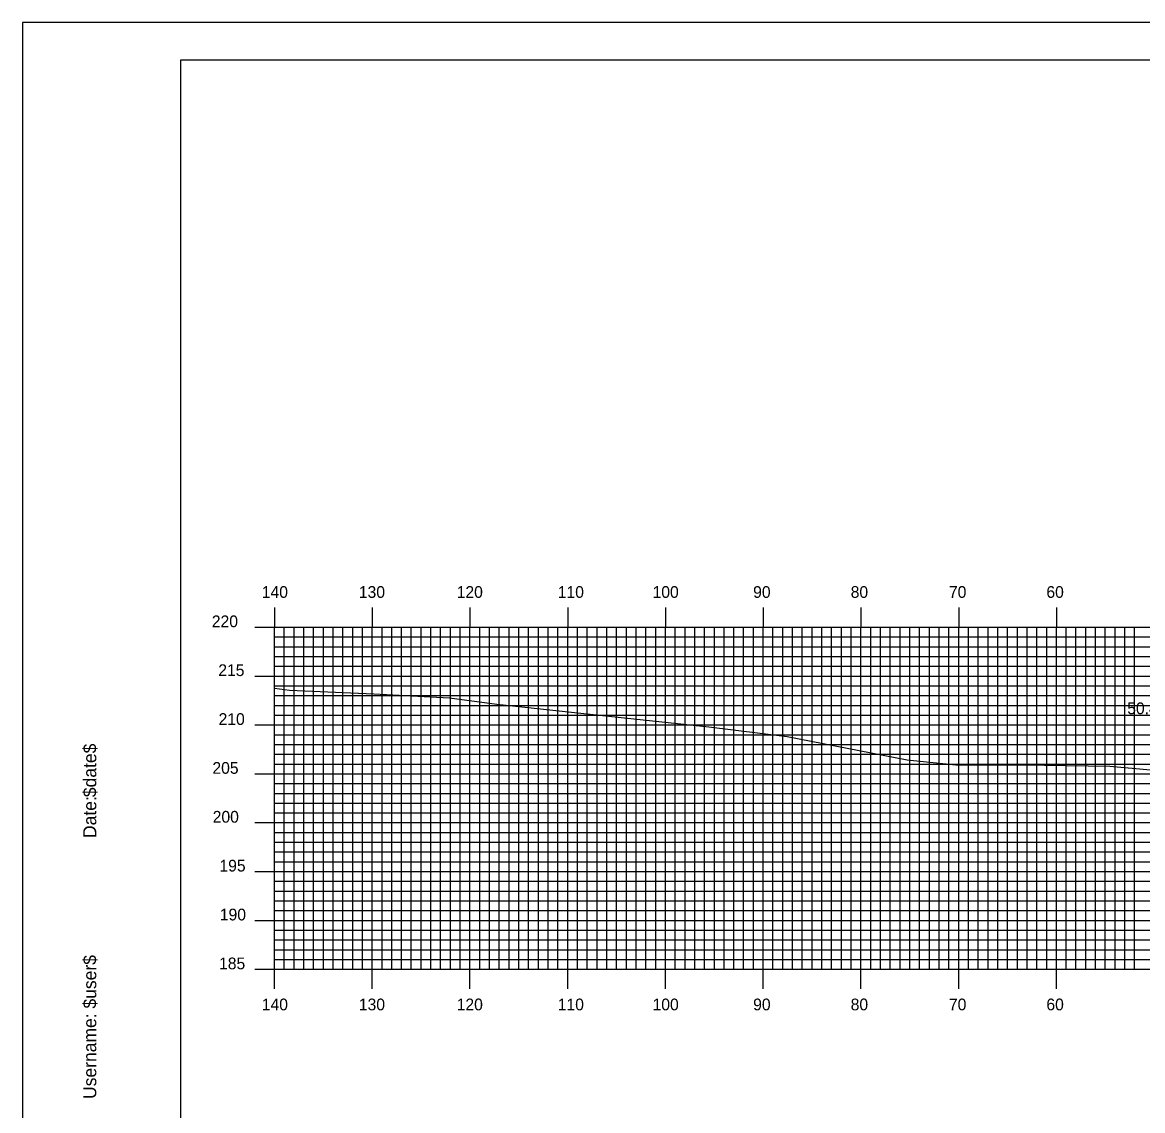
# Model space of a CAD drawing. Extents: x 1815702 to 1816046, y 442591 to 442811.
# Drawn here: x 1815702.3 to 1815816.9, y 442699.2 to 442810.5 of the extents above; entities that cross this region are included whole.
import ezdxf

# ---------------------------------------------------------------- set-up
doc = ezdxf.new("R2010")
doc.units = 0
for name, color, linetype in [('BORDER', 7, 'Continuous'), ('D_Text_Standard', 7, 'Continuous'), ('H_V ANNOTATION', 7, 'Continuous'), ('MAJOR', 7, 'Continuous'), ('MINOR', 7, 'Continuous'), ('PLOT BOUNDARY', 7, 'Continuous'), ('S_Roadway_Centerline', 7, 'Continuous')]:
    doc.layers.add(name, color=color, linetype=linetype)

msp = doc.modelspace()

# ---------------------------------------------------------------- linework, layer by layer
at = {"layer": 'BORDER'}
msp.add_lwpolyline([(1815718.45, 442596.67), (1816038.45, 442596.67), (1816038.45, 442806.67), (1815718.45, 442806.67)], close=True, dxfattribs=at)
at = {"layer": 'MAJOR'}
for p, q in [((1815728.05, 442750.67), (1815728.05, 442748.67)), ((1815738.05, 442750.67), (1815738.05, 442748.67)), ((1815748.05, 442750.67), (1815748.05, 442748.67)), ((1815758.05, 442750.67), (1815758.05, 442748.67)), ((1815768.05, 442750.67), (1815768.05, 442748.67)), ((1815778.05, 442750.67), (1815778.05, 442748.67)), ((1815788.05, 442750.67), (1815788.05, 442748.67)), ((1815798.05, 442750.67), (1815798.05, 442748.67)), ((1815808.05, 442750.67), (1815808.05, 442748.67)), ((1815726.04, 442748.67), (1815728.05, 442748.67)), ((1815728.05, 442748.67), (1816008.05, 442748.67)), ((1815728.05, 442713.67), (1815728.05, 442748.67)), ((1815728.05, 442713.67), (1815728.05, 442748.67)), ((1815728.05, 442748.67), (1816008.05, 442748.67)), ((1815738.05, 442713.67), (1815738.05, 442748.67)), ((1815748.05, 442713.67), (1815748.05, 442748.67)), ((1815758.05, 442713.67), (1815758.05, 442748.67)), ((1815768.05, 442713.67), (1815768.05, 442748.67)), ((1815778.05, 442713.67), (1815778.05, 442748.67)), ((1815788.05, 442713.67), (1815788.05, 442748.67)), ((1815798.05, 442713.67), (1815798.05, 442748.67)), ((1815808.05, 442713.67), (1815808.05, 442748.67)), ((1815726.04, 442743.67), (1815728.05, 442743.67)), ((1815728.05, 442743.67), (1816008.05, 442743.67)), ((1815726.04, 442738.67), (1815728.05, 442738.67)), ((1815728.05, 442738.67), (1816008.05, 442738.67)), ((1815726.04, 442733.67), (1815728.05, 442733.67)), ((1815728.05, 442733.67), (1816008.05, 442733.67)), ((1815726.04, 442728.67), (1815728.05, 442728.67)), ((1815728.05, 442728.67), (1816008.05, 442728.67)), ((1815726.04, 442723.67), (1815728.05, 442723.67)), ((1815728.05, 442723.67), (1816008.05, 442723.67)), ((1815726.04, 442718.67), (1815728.05, 442718.67)), ((1815728.05, 442718.67), (1816008.05, 442718.67)), ((1815726.04, 442713.67), (1815728.05, 442713.67)), ((1815728.05, 442713.67), (1816008.05, 442713.67)), ((1815728.05, 442713.67), (1816008.05, 442713.67)), ((1815728.05, 442711.66), (1815728.05, 442713.67)), ((1815738.05, 442711.66), (1815738.05, 442713.67)), ((1815748.05, 442711.66), (1815748.05, 442713.67)), ((1815758.05, 442711.66), (1815758.05, 442713.67)), ((1815768.05, 442711.66), (1815768.05, 442713.67)), ((1815778.05, 442711.66), (1815778.05, 442713.67)), ((1815788.05, 442711.66), (1815788.05, 442713.67)), ((1815798.05, 442711.66), (1815798.05, 442713.67)), ((1815808.05, 442711.66), (1815808.05, 442713.67))]:
    msp.add_line(p, q, dxfattribs=at)
at = {"layer": 'MINOR'}
for p, q in [((1815729.05, 442713.67), (1815729.05, 442748.67)), ((1815730.05, 442713.67), (1815730.05, 442748.67)), ((1815731.05, 442713.67), (1815731.05, 442748.67)), ((1815732.05, 442713.67), (1815732.05, 442748.67)), ((1815733.05, 442713.67), (1815733.05, 442748.67)), ((1815734.05, 442713.67), (1815734.05, 442748.67)), ((1815735.05, 442713.67), (1815735.05, 442748.67)), ((1815736.05, 442713.67), (1815736.05, 442748.67)), ((1815737.05, 442713.67), (1815737.05, 442748.67)), ((1815739.05, 442713.67), (1815739.05, 442748.67)), ((1815740.05, 442713.67), (1815740.05, 442748.67)), ((1815741.05, 442713.67), (1815741.05, 442748.67)), ((1815742.05, 442713.67), (1815742.05, 442748.67)), ((1815743.05, 442713.67), (1815743.05, 442748.67)), ((1815744.05, 442713.67), (1815744.05, 442748.67)), ((1815745.05, 442713.67), (1815745.05, 442748.67)), ((1815746.05, 442713.67), (1815746.05, 442748.67)), ((1815747.05, 442713.67), (1815747.05, 442748.67)), ((1815749.05, 442713.67), (1815749.05, 442748.67)), ((1815750.05, 442713.67), (1815750.05, 442748.67)), ((1815751.05, 442713.67), (1815751.05, 442748.67)), ((1815752.05, 442713.67), (1815752.05, 442748.67)), ((1815753.05, 442713.67), (1815753.05, 442748.67)), ((1815754.05, 442713.67), (1815754.05, 442748.67)), ((1815755.05, 442713.67), (1815755.05, 442748.67)), ((1815756.05, 442713.67), (1815756.05, 442748.67)), ((1815757.05, 442713.67), (1815757.05, 442748.67)), ((1815759.05, 442713.67), (1815759.05, 442748.67)), ((1815760.05, 442713.67), (1815760.05, 442748.67)), ((1815761.05, 442713.67), (1815761.05, 442748.67)), ((1815762.05, 442713.67), (1815762.05, 442748.67)), ((1815763.05, 442713.67), (1815763.05, 442748.67)), ((1815764.05, 442713.67), (1815764.05, 442748.67)), ((1815765.05, 442713.67), (1815765.05, 442748.67)), ((1815766.05, 442713.67), (1815766.05, 442748.67)), ((1815767.05, 442713.67), (1815767.05, 442748.67)), ((1815769.05, 442713.67), (1815769.05, 442748.67)), ((1815770.05, 442713.67), (1815770.05, 442748.67)), ((1815771.05, 442713.67), (1815771.05, 442748.67)), ((1815772.05, 442713.67), (1815772.05, 442748.67)), ((1815773.05, 442713.67), (1815773.05, 442748.67)), ((1815774.05, 442713.67), (1815774.05, 442748.67)), ((1815775.05, 442713.67), (1815775.05, 442748.67)), ((1815776.05, 442713.67), (1815776.05, 442748.67)), ((1815777.05, 442713.67), (1815777.05, 442748.67)), ((1815779.05, 442713.67), (1815779.05, 442748.67)), ((1815780.05, 442713.67), (1815780.05, 442748.67)), ((1815781.05, 442713.67), (1815781.05, 442748.67)), ((1815782.05, 442713.67), (1815782.05, 442748.67)), ((1815783.05, 442713.67), (1815783.05, 442748.67)), ((1815784.05, 442713.67), (1815784.05, 442748.67)), ((1815785.05, 442713.67), (1815785.05, 442748.67)), ((1815786.05, 442713.67), (1815786.05, 442748.67)), ((1815787.05, 442713.67), (1815787.05, 442748.67)), ((1815789.05, 442713.67), (1815789.05, 442748.67)), ((1815790.05, 442713.67), (1815790.05, 442748.67)), ((1815791.05, 442713.67), (1815791.05, 442748.67)), ((1815792.05, 442713.67), (1815792.05, 442748.67)), ((1815793.05, 442713.67), (1815793.05, 442748.67)), ((1815794.05, 442713.67), (1815794.05, 442748.67)), ((1815795.05, 442713.67), (1815795.05, 442748.67)), ((1815796.05, 442713.67), (1815796.05, 442748.67)), ((1815797.05, 442713.67), (1815797.05, 442748.67)), ((1815799.05, 442713.67), (1815799.05, 442748.67)), ((1815800.05, 442713.67), (1815800.05, 442748.67)), ((1815801.05, 442713.67), (1815801.05, 442748.67)), ((1815802.05, 442713.67), (1815802.05, 442748.67)), ((1815803.05, 442713.67), (1815803.05, 442748.67)), ((1815804.05, 442713.67), (1815804.05, 442748.67)), ((1815805.05, 442713.67), (1815805.05, 442748.67)), ((1815806.05, 442713.67), (1815806.05, 442748.67)), ((1815807.05, 442713.67), (1815807.05, 442748.67)), ((1815809.05, 442713.67), (1815809.05, 442748.67)), ((1815810.05, 442713.67), (1815810.05, 442748.67)), ((1815811.05, 442713.67), (1815811.05, 442748.67)), ((1815812.05, 442713.67), (1815812.05, 442748.67)), ((1815813.05, 442713.67), (1815813.05, 442748.67)), ((1815814.05, 442713.67), (1815814.05, 442748.67)), ((1815815.05, 442713.67), (1815815.05, 442748.67)), ((1815816.05, 442713.67), (1815816.05, 442748.67)), ((1815728.05, 442747.67), (1816008.05, 442747.67)), ((1815728.05, 442747.67), (1815730.05, 442747.67)), ((1815728.05, 442746.67), (1816008.05, 442746.67)), ((1815728.05, 442746.67), (1815730.05, 442746.67)), ((1815728.05, 442745.67), (1816008.05, 442745.67)), ((1815728.05, 442745.67), (1815730.05, 442745.67)), ((1815728.05, 442744.67), (1816008.05, 442744.67)), ((1815728.05, 442744.67), (1815730.05, 442744.67)), ((1815728.05, 442742.67), (1816008.05, 442742.67)), ((1815728.05, 442742.67), (1815730.05, 442742.67)), ((1815728.05, 442741.67), (1816008.05, 442741.67)), ((1815728.05, 442741.67), (1815730.05, 442741.67)), ((1815728.05, 442740.67), (1816008.05, 442740.67)), ((1815728.05, 442740.67), (1815730.05, 442740.67)), ((1815728.05, 442739.67), (1816008.05, 442739.67)), ((1815728.05, 442739.67), (1815730.05, 442739.67)), ((1815728.05, 442737.67), (1816008.05, 442737.67)), ((1815728.05, 442737.67), (1815730.05, 442737.67)), ((1815728.05, 442736.67), (1816008.05, 442736.67)), ((1815728.05, 442736.67), (1815730.05, 442736.67)), ((1815728.05, 442735.67), (1816008.05, 442735.67)), ((1815728.05, 442735.67), (1815730.05, 442735.67)), ((1815728.05, 442734.67), (1816008.05, 442734.67)), ((1815728.05, 442734.67), (1815730.05, 442734.67)), ((1815728.05, 442732.67), (1816008.05, 442732.67)), ((1815728.05, 442732.67), (1815730.05, 442732.67)), ((1815728.05, 442731.67), (1816008.05, 442731.67)), ((1815728.05, 442731.67), (1815730.05, 442731.67)), ((1815728.05, 442730.67), (1816008.05, 442730.67)), ((1815728.05, 442730.67), (1815730.05, 442730.67)), ((1815728.05, 442729.67), (1816008.05, 442729.67)), ((1815728.05, 442729.67), (1815730.05, 442729.67)), ((1815728.05, 442727.67), (1816008.05, 442727.67)), ((1815728.05, 442727.67), (1815730.05, 442727.67)), ((1815728.05, 442726.67), (1816008.05, 442726.67)), ((1815728.05, 442726.67), (1815730.05, 442726.67)), ((1815728.05, 442725.67), (1816008.05, 442725.67)), ((1815728.05, 442725.67), (1815730.05, 442725.67)), ((1815728.05, 442724.67), (1816008.05, 442724.67)), ((1815728.05, 442724.67), (1815730.05, 442724.67)), ((1815728.05, 442722.67), (1816008.05, 442722.67)), ((1815728.05, 442722.67), (1815730.05, 442722.67)), ((1815728.05, 442721.67), (1816008.05, 442721.67)), ((1815728.05, 442721.67), (1815730.05, 442721.67)), ((1815728.05, 442720.67), (1816008.05, 442720.67)), ((1815728.05, 442720.67), (1815730.05, 442720.67)), ((1815728.05, 442719.67), (1816008.05, 442719.67)), ((1815728.05, 442719.67), (1815730.05, 442719.67)), ((1815728.05, 442717.67), (1816008.05, 442717.67)), ((1815728.05, 442717.67), (1815730.05, 442717.67)), ((1815728.05, 442716.67), (1816008.05, 442716.67)), ((1815728.05, 442716.67), (1815730.05, 442716.67)), ((1815728.05, 442715.67), (1816008.05, 442715.67)), ((1815728.05, 442715.67), (1815730.05, 442715.67)), ((1815728.05, 442714.67), (1816008.05, 442714.67)), ((1815728.05, 442714.67), (1815730.05, 442714.67))]:
    msp.add_line(p, q, dxfattribs=at)
at = {"layer": 'PLOT BOUNDARY'}
msp.add_lwpolyline([(1815702.26, 442590.55), (1816042.26, 442590.55), (1816042.26, 442810.55), (1815702.26, 442810.55)], close=True, dxfattribs=at)
at = {"layer": 'S_Roadway_Centerline'}
msp.add_lwpolyline([(1815728.05, 442742.44), (1815729.57, 442742.24), (1815738.23, 442741.86), (1815745.94, 442741.45), (1815750.81, 442740.8), (1815763.22, 442739.45), (1815772.49, 442738.46), (1815780.49, 442737.48), (1815792.77, 442735.09), (1815797.76, 442734.58), (1815806.84, 442734.56), (1815813.52, 442734.44), (1815817.67, 442734.08)], dxfattribs=at)

# ---------------------------------------------------------------- texts
at = {"layer": 'BORDER'}
for s, p in [('$date$', (1815709.82, 442731.28)), ('Date:', (1815709.82, 442727.1)), ('$user$', (1815709.82, 442709.65)), ('Username:', (1815709.82, 442700.4))]:
    msp.add_text(s, height=1.339, rotation=90, dxfattribs=at).set_placement(p)
at = {"layer": 'D_Text_Standard'}
msp.add_text("50.4'", height=1.2, dxfattribs=at).set_placement((1815815.29, 442739.77))
at = {"layer": 'H_V ANNOTATION'}
for s, p in [('140', (1815726.75, 442751.67)), ('130', (1815736.68, 442751.67)), ('120', (1815746.69, 442751.67)), ('110', (1815757.03, 442751.67)), ('100', (1815766.73, 442751.67)), ('90', (1815777.02, 442751.67)), ('80', (1815787, 442751.67)), ('70', (1815797.05, 442751.67)), ('60', (1815807.02, 442751.67)), ('220', (1815721.64, 442748.67)), ('215', (1815722.3, 442743.67)), ('210', (1815722.33, 442738.67)), ('205', (1815721.7, 442733.67)), ('200', (1815721.73, 442728.67)), ('195', (1815722.42, 442723.67)), ('190', (1815722.46, 442718.67)), ('185', (1815722.38, 442713.67)), ('140', (1815726.75, 442709.47)), ('130', (1815736.68, 442709.47)), ('120', (1815746.69, 442709.47)), ('110', (1815757.03, 442709.47)), ('100', (1815766.73, 442709.47)), ('90', (1815777.02, 442709.47)), ('80', (1815787, 442709.47)), ('70', (1815797.05, 442709.47)), ('60', (1815807.02, 442709.47))]:
    msp.add_text(s, height=1.2, dxfattribs=at).set_placement(p)
at = {"layer": 'MAJOR'}
msp.add_text('-', height=0.012, dxfattribs=at).set_placement((1815728.04, 442713.67))

doc.saveas('drawing.dxf')
